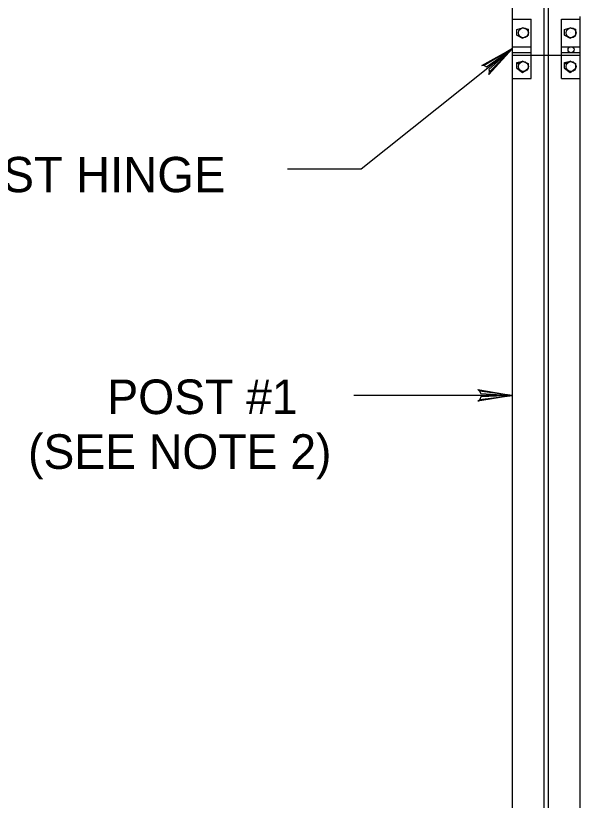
# Model space of a CAD drawing. Extents: x 637580 to 641008, y 294594 to 295782.
# Drawn here: x 637895.1 to 637944.1, y 295481.5 to 295549.6 of the extents above; entities that cross this region are included whole.
import ezdxf

# ---------------------------------------------------------------- set-up
doc = ezdxf.new("R2010")
doc.units = 0
for name, color, linetype in [('1', 7, 'Continuous'), ('2', 7, 'Continuous'), ('3', 7, 'Continuous')]:
    doc.layers.add(name, color=color, linetype=linetype)

# ---------------------------------------------------------------- blocks, each defined once
blk = doc.blocks.new('RARROW')
at = {"layer": '3'}
blk.add_lwpolyline([(-2.2695, 0.285), (-2.184875, 0.12075), (0, 0), (-2.2695, 0.285), (-2.38575, 0.384625), (0, 0), (-2.183125, -0.108), (-2.262875, -0.2705), (0, 0), (-2.38575, -0.379125), (-2.262875, -0.2705)], dxfattribs=at)

msp = doc.modelspace()

# ---------------------------------------------------------------- linework, layer by layer
at = {"layer": '2'}
for p, q in [((637938.187, 295549.501), (637938.187, 295676.876)), ((637940.937, 295461.876), (637940.937, 295676.876)), ((637941.312, 295461.876), (637941.312, 295676.876)), ((637938.187, 295469.501), (637938.187, 295549.501)), ((637938.187, 295549.251), (637939.812, 295549.251)), ((637939.812, 295544.126), (637939.812, 295549.251)), ((637942.437, 295549.251), (637944.062, 295549.251)), ((637942.437, 295544.126), (637942.437, 295549.251)), ((637944.062, 295469.501), (637944.062, 295549.501)), ((637938.562, 295548.376), (637939.062, 295548.501)), ((637938.562, 295548.376), (637939.062, 295548.501)), ((637938.562, 295547.876), (637938.562, 295548.376)), ((637938.562, 295547.876), (637938.562, 295548.376)), ((637939.062, 295548.501), (637939.562, 295548.376)), ((637939.562, 295548.376), (637939.062, 295548.501)), ((637939.562, 295547.876), (637939.562, 295548.376)), ((637939.562, 295547.876), (637939.562, 295548.376)), ((637942.687, 295548.376), (637943.187, 295548.501)), ((637942.687, 295548.376), (637943.187, 295548.501)), ((637942.687, 295547.876), (637942.687, 295548.376)), ((637942.687, 295547.876), (637942.687, 295548.376)), ((637943.187, 295548.501), (637943.687, 295548.376)), ((637943.687, 295548.376), (637943.187, 295548.501)), ((637943.687, 295547.876), (637943.687, 295548.376)), ((637943.687, 295547.876), (637943.687, 295548.376)), ((637938.562, 295547.876), (637939.062, 295547.626)), ((637939.062, 295547.626), (637938.562, 295547.876)), ((637939.062, 295548.126), (637939.062, 295548.126)), ((637939.062, 295547.626), (637939.562, 295547.876)), ((637939.062, 295547.626), (637939.562, 295547.876)), ((637942.687, 295547.876), (637943.187, 295547.626)), ((637943.187, 295547.626), (637942.687, 295547.876)), ((637943.187, 295548.126), (637943.187, 295548.126)), ((637943.187, 295547.626), (637943.687, 295547.876)), ((637943.187, 295547.626), (637943.687, 295547.876)), ((637938.187, 295546.876), (637939.812, 295546.876)), ((637942.437, 295546.876), (637944.062, 295546.876)), ((637938.187, 295546.725), (637925.062, 295536.251)), ((637938.187, 295546.376), (637939.812, 295546.376)), ((637938.187, 295546.126), (637939.812, 295546.126)), ((637938.187, 295546.126), (637938.187, 295546.126)), ((637939.812, 295546.126), (637942.437, 295546.126)), ((637942.437, 295546.376), (637944.062, 295546.376)), ((637942.437, 295546.126), (637944.062, 295546.126)), ((637943.187, 295546.751), (637943.187, 295546.751)), ((637938.562, 295545.501), (637939.062, 295545.626)), ((637938.562, 295545.376), (637939.062, 295545.626)), ((637938.562, 295545.001), (637938.562, 295545.501)), ((637939.062, 295545.626), (637939.562, 295545.376)), ((637939.562, 295545.376), (637939.062, 295545.626)), ((637942.687, 295545.501), (637943.187, 295545.626)), ((637942.687, 295545.376), (637943.187, 295545.626)), ((637942.687, 295545.001), (637942.687, 295545.501)), ((637943.187, 295545.626), (637943.687, 295545.376)), ((637943.687, 295545.376), (637943.187, 295545.626)), ((637938.562, 295545.001), (637938.562, 295545.376)), ((637938.562, 295545.001), (637939.062, 295544.626)), ((637939.062, 295544.626), (637938.562, 295545.001)), ((637939.062, 295545.251), (637939.062, 295545.251)), ((637939.062, 295544.626), (637939.562, 295545.001)), ((637939.062, 295544.626), (637939.562, 295545.001)), ((637939.562, 295545.001), (637939.562, 295545.376)), ((637939.562, 295545.001), (637939.562, 295545.376)), ((637942.687, 295545.001), (637942.687, 295545.376)), ((637942.687, 295545.001), (637943.187, 295544.626)), ((637943.187, 295544.626), (637942.687, 295545.001)), ((637943.187, 295545.251), (637943.187, 295545.251)), ((637943.187, 295544.626), (637943.687, 295545.001)), ((637943.187, 295544.626), (637943.687, 295545.001)), ((637943.687, 295545.001), (637943.687, 295545.376)), ((637943.687, 295545.001), (637943.687, 295545.376)), ((637938.187, 295544.126), (637939.812, 295544.126)), ((637942.437, 295544.126), (637944.062, 295544.126)), ((637925.062, 295536.251), (637918.687, 295536.251)), ((637938.187, 295516.626), (637924.437, 295516.626))]:
    msp.add_line(p, q, dxfattribs=at)
for centre, major_axis in [((637939.128, 295548.071), (0, -0.432)), ((637943.264, 295548.071), (0, -0.432)), ((637943.264, 295546.611), (0, 0.265)), ((637939.128, 295545.153), (0, -0.432)), ((637943.264, 295545.153), (0, -0.432))]:
    msp.add_ellipse(centre, major_axis=major_axis, ratio=0.996388, dxfattribs=at)

# ---------------------------------------------------------------- block references
at = {"layer": '2', "xscale": 1.2574347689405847, "yscale": 1.3092961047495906, "rotation": 38.427083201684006}
msp.add_blockref('RARROW', (637938.187, 295546.725), dxfattribs=at)
at = {"layer": '2', "xscale": 1.2574347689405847, "yscale": 1.3092961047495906}
msp.add_blockref('RARROW', (637938.187, 295516.626), dxfattribs=at)

# ---------------------------------------------------------------- texts
at = {"layer": '1'}
for s, height, p in [('POST HINGE', 3.0608, (637888.062, 295534.251)), ('(SEE NOTE 2)', 3, (637896.187, 295510.251))]:
    msp.add_text(s, height=height, dxfattribs=at).set_placement(p)
at = {"layer": '3'}
msp.add_text('POST #1', height=3, dxfattribs=at).set_placement((637903.062, 295515.001))

doc.saveas('drawing.dxf')
